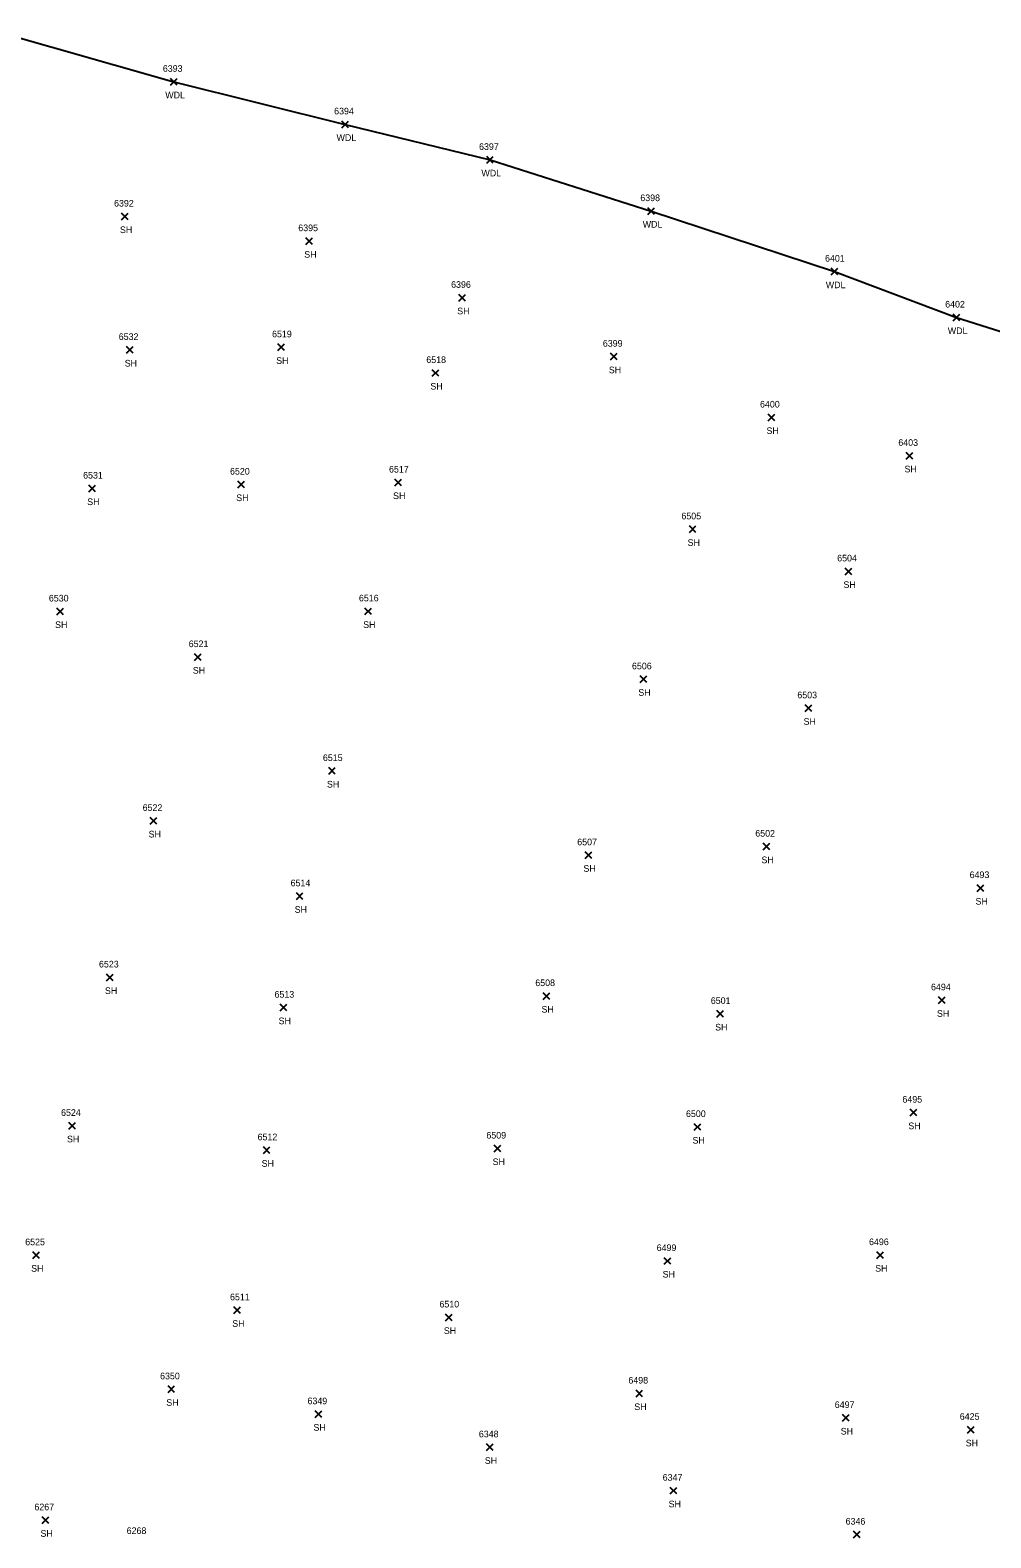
# Model space of a CAD drawing. Extents: x 1678863 to 1683592, y 407783 to 418211.
# Drawn here: x 1679783.6 to 1680073.6, y 409484.1 to 409938.9 of the extents above; entities that cross this region are included whole.
import ezdxf

# ---------------------------------------------------------------- set-up
doc = ezdxf.new("R2010")
doc.units = 0
for name, color, linetype in [('L_A', 7, 'Continuous'), ('L_I', 7, 'Continuous'), ('L_TIC', 7, 'Continuous'), ('LAWA', 7, 'Continuous')]:
    doc.layers.add(name, color=color, linetype=linetype)

msp = doc.modelspace()

# ---------------------------------------------------------------- linework, layer by layer
at = {"layer": 'L_TIC'}
for points in [[(1679825.93, 409922.32), (1679827.93, 409924.32)], [(1679827.93, 409922.32), (1679825.93, 409924.32)], [(1679877.64, 409909.47), (1679879.64, 409911.47)], [(1679879.64, 409909.47), (1679877.64, 409911.47)], [(1679921.38, 409898.77), (1679923.38, 409900.77)], [(1679923.38, 409898.77), (1679921.38, 409900.77)], [(1679811.19, 409881.67), (1679813.19, 409883.67)], [(1679813.19, 409881.67), (1679811.19, 409883.67)], [(1679970.06, 409883.31), (1679972.06, 409885.31)], [(1679972.06, 409883.31), (1679970.06, 409885.31)], [(1679866.82, 409874.25), (1679868.82, 409876.25)], [(1679868.82, 409874.25), (1679866.82, 409876.25)], [(1680025.33, 409865.05), (1680027.33, 409867.05)], [(1680027.33, 409865.05), (1680025.33, 409867.05)], [(1679913, 409857.16), (1679915, 409859.16)], [(1679915, 409857.16), (1679913, 409859.16)], [(1680062.16, 409851.21), (1680064.16, 409853.21)], [(1680064.16, 409851.21), (1680062.16, 409853.21)], [(1679812.62, 409841.42), (1679814.62, 409843.42)], [(1679814.62, 409841.42), (1679812.62, 409843.42)], [(1679858.34, 409842.22), (1679860.34, 409844.22)], [(1679860.34, 409842.22), (1679858.34, 409844.22)], [(1679958.75, 409839.4), (1679960.75, 409841.4)], [(1679960.75, 409839.4), (1679958.75, 409841.4)], [(1679904.89, 409834.47), (1679906.89, 409836.47)], [(1679906.89, 409834.47), (1679904.89, 409836.47)], [(1680006.35, 409821.05), (1680008.35, 409823.05)], [(1680008.35, 409821.05), (1680006.35, 409823.05)], [(1680048.02, 409809.49), (1680050.02, 409811.49)], [(1680050.02, 409809.49), (1680048.02, 409811.49)], [(1679801.3, 409799.62), (1679803.3, 409801.62)], [(1679803.3, 409799.62), (1679801.3, 409801.62)], [(1679846.29, 409800.82), (1679848.29, 409802.82)], [(1679848.29, 409800.82), (1679846.29, 409802.82)], [(1679893.63, 409801.43), (1679895.63, 409803.43)], [(1679895.63, 409801.43), (1679893.63, 409803.43)], [(1679982.55, 409787.32), (1679984.55, 409789.32)], [(1679984.55, 409787.32), (1679982.55, 409789.32)], [(1680029.57, 409774.62), (1680031.57, 409776.62)], [(1680031.57, 409774.62), (1680029.57, 409776.62)], [(1679791.61, 409762.54), (1679793.61, 409764.54)], [(1679793.61, 409762.54), (1679791.61, 409764.54)], [(1679884.6, 409762.57), (1679886.6, 409764.57)], [(1679886.6, 409762.57), (1679884.6, 409764.57)], [(1679833.17, 409748.77), (1679835.17, 409750.77)], [(1679835.17, 409748.77), (1679833.17, 409750.77)], [(1679967.67, 409742.09), (1679969.67, 409744.09)], [(1679969.67, 409742.09), (1679967.67, 409744.09)], [(1680017.53, 409733.34), (1680019.53, 409735.34)], [(1680019.53, 409733.34), (1680017.53, 409735.34)], [(1679873.68, 409714.42), (1679875.68, 409716.42)], [(1679875.68, 409714.42), (1679873.68, 409716.42)], [(1679819.84, 409699.36), (1679821.84, 409701.36)], [(1679821.84, 409699.36), (1679819.84, 409701.36)], [(1680004.83, 409691.6), (1680006.83, 409693.6)], [(1680006.83, 409691.6), (1680004.83, 409693.6)], [(1679951.09, 409689), (1679953.09, 409691)], [(1679953.09, 409689), (1679951.09, 409691)], [(1679863.93, 409676.64), (1679865.93, 409678.64)], [(1679865.93, 409676.64), (1679863.93, 409678.64)], [(1680069.47, 409679.1), (1680071.47, 409681.1)], [(1680071.47, 409679.1), (1680069.47, 409681.1)], [(1679806.65, 409652.14), (1679808.65, 409654.14)], [(1679808.65, 409652.14), (1679806.65, 409654.14)], [(1679938.44, 409646.52), (1679940.44, 409648.52)], [(1679940.44, 409646.52), (1679938.44, 409648.52)], [(1680057.8, 409645.25), (1680059.8, 409647.25)], [(1680059.8, 409645.25), (1680057.8, 409647.25)], [(1679859.07, 409643.03), (1679861.07, 409645.03)], [(1679861.07, 409643.03), (1679859.07, 409645.03)], [(1679990.85, 409641.13), (1679992.85, 409643.13)], [(1679992.85, 409641.13), (1679990.85, 409643.13)], [(1680049.17, 409611.36), (1680051.17, 409613.36)], [(1680051.17, 409611.36), (1680049.17, 409613.36)], [(1679795.21, 409607.38), (1679797.21, 409609.38)], [(1679797.21, 409607.38), (1679795.21, 409609.38)], [(1679984.01, 409607.02), (1679986.01, 409609.02)], [(1679986.01, 409607.02), (1679984.01, 409609.02)], [(1679853.96, 409600.02), (1679855.96, 409602.02)], [(1679855.96, 409600.02), (1679853.96, 409602.02)], [(1679923.68, 409600.53), (1679925.68, 409602.53)], [(1679925.68, 409600.53), (1679923.68, 409602.53)], [(1679784.38, 409568.35), (1679786.38, 409570.35)], [(1679786.38, 409568.35), (1679784.38, 409570.35)], [(1680039.15, 409568.38), (1680041.15, 409570.38)], [(1680041.15, 409568.38), (1680039.15, 409570.38)], [(1679975, 409566.6), (1679977, 409568.6)], [(1679977, 409566.6), (1679975, 409568.6)], [(1679845.07, 409551.74), (1679847.07, 409553.74)], [(1679847.07, 409551.74), (1679845.07, 409553.74)], [(1679908.95, 409549.58), (1679910.95, 409551.58)], [(1679910.95, 409549.58), (1679908.95, 409551.58)], [(1679825.18, 409527.91), (1679827.18, 409529.91)], [(1679827.18, 409527.91), (1679825.18, 409529.91)], [(1679966.45, 409526.63), (1679968.45, 409528.63)], [(1679968.45, 409526.63), (1679966.45, 409528.63)], [(1679869.6, 409520.39), (1679871.6, 409522.39)], [(1679871.6, 409520.39), (1679869.6, 409522.39)], [(1680028.75, 409519.25), (1680030.75, 409521.25)], [(1680030.75, 409519.25), (1680028.75, 409521.25)], [(1680066.49, 409515.69), (1680068.49, 409517.69)], [(1680068.49, 409515.69), (1680066.49, 409517.69)], [(1679921.32, 409510.41), (1679923.32, 409512.41)], [(1679923.32, 409510.41), (1679921.32, 409512.41)], [(1679976.81, 409497.31), (1679978.81, 409499.31)], [(1679978.81, 409497.31), (1679976.81, 409499.31)], [(1679787.2, 409488.4), (1679789.2, 409490.4)], [(1679789.2, 409488.4), (1679787.2, 409490.4)], [(1680032.08, 409484.08), (1680034.08, 409486.08)], [(1680034.08, 409484.08), (1680032.08, 409486.08)]]:
    msp.add_lwpolyline(points, dxfattribs=at)
at = {"layer": 'LAWA'}
msp.add_lwpolyline([(1679772.13, 409938.89), (1679826.93, 409923.32), (1679878.64, 409910.47), (1679922.38, 409899.77), (1679971.06, 409884.31), (1680026.33, 409866.05), (1680063.16, 409852.21), (1680119.91, 409834.32), (1680167.52, 409815.73), (1680215.19, 409801.86), (1680258.97, 409790.94), (1680289.52, 409781.41), (1680315.18, 409768.89), (1680323.05, 409758.38), (1680327.93, 409761.51), (1680342.05, 409772.19), (1680349.85, 409770.79), (1680397.53, 409750.97)], dxfattribs=at)

# ---------------------------------------------------------------- texts
at = {"layer": 'L_A'}
for s, p in [('WDL', (1679824.35, 409918.32)), ('WDL', (1679876.06, 409905.47)), ('WDL', (1679919.79, 409894.77)), ('SH', (1679810.68, 409877.67)), ('WDL', (1679968.48, 409879.31)), ('SH', (1679866.31, 409870.25)), ('WDL', (1680023.74, 409861.05)), ('SH', (1679912.49, 409853.16)), ('WDL', (1680060.57, 409847.21)), ('SH', (1679812.11, 409837.42)), ('SH', (1679857.83, 409838.22)), ('SH', (1679958.24, 409835.4)), ('SH', (1679904.38, 409830.47)), ('SH', (1680005.84, 409817.05)), ('SH', (1680047.5, 409805.49)), ('SH', (1679800.79, 409795.62)), ('SH', (1679845.78, 409796.82)), ('SH', (1679893.12, 409797.43)), ('SH', (1679982.03, 409783.32)), ('SH', (1680029.06, 409770.62)), ('SH', (1679791.1, 409758.54)), ('SH', (1679884.09, 409758.57)), ('SH', (1679832.66, 409744.77)), ('SH', (1679967.16, 409738.09)), ('SH', (1680017.02, 409729.34)), ('SH', (1679873.16, 409710.42)), ('SH', (1679819.32, 409695.36)), ('SH', (1679950.58, 409685)), ('SH', (1680004.32, 409687.6)), ('SH', (1679863.42, 409672.64)), ('SH', (1680068.95, 409675.1)), ('SH', (1679806.14, 409648.14)), ('SH', (1679937.93, 409642.52)), ('SH', (1680057.29, 409641.25)), ('SH', (1679858.56, 409639.03)), ('SH', (1679990.34, 409637.13)), ('SH', (1679794.69, 409603.38)), ('SH', (1680048.66, 409607.36)), ('SH', (1679983.5, 409603.02)), ('SH', (1679853.45, 409596.02)), ('SH', (1679923.17, 409596.53)), ('SH', (1679783.87, 409564.35)), ('SH', (1679974.49, 409562.6)), ('SH', (1680038.64, 409564.38)), ('SH', (1679844.56, 409547.74)), ('SH', (1679908.44, 409545.58)), ('SH', (1679824.67, 409523.91)), ('SH', (1679965.94, 409522.63)), ('SH', (1679869.09, 409516.39)), ('SH', (1680028.24, 409515.25)), ('SH', (1680065.98, 409511.69)), ('SH', (1679920.81, 409506.41)), ('SH', (1679976.3, 409493.31)), ('SH', (1679786.69, 409484.4))]:
    msp.add_text(s, height=2, dxfattribs=at).set_placement(p)
at = {"layer": 'L_I'}
for s, p in [('6393', (1679823.62, 409926.32)), ('6394', (1679875.33, 409913.47)), ('6397', (1679919.07, 409902.77)), ('6392', (1679808.89, 409885.67)), ('6398', (1679967.75, 409887.31)), ('6395', (1679864.51, 409878.25)), ('6401', (1680023.51, 409869.05)), ('6396', (1679910.64, 409861.16)), ('6402', (1680059.77, 409855.21)), ('6532', (1679810.31, 409845.42)), ('6519', (1679856.59, 409846.22)), ('6399', (1679956.44, 409843.4)), ('6518', (1679903.15, 409838.47)), ('6400', (1680003.88, 409825.05)), ('6403', (1680045.63, 409813.49)), ('6531', (1679799.56, 409803.62)), ('6520', (1679843.9, 409804.82)), ('6517', (1679891.89, 409805.43)), ('6505', (1679980.16, 409791.32)), ('6504', (1680027.18, 409778.62)), ('6530', (1679789.22, 409766.54)), ('6516', (1679882.81, 409766.57)), ('6521', (1679831.43, 409752.77)), ('6506', (1679965.23, 409746.09)), ('6503', (1680015.15, 409737.34)), ('6515', (1679871.94, 409718.42)), ('6522', (1679817.53, 409703.36)), ('6502', (1680002.45, 409695.6)), ('6507', (1679948.71, 409693)), ('6514', (1679862.19, 409680.64)), ('6493', (1680067.16, 409683.1)), ('6523', (1679804.34, 409656.14)), ('6508', (1679936.05, 409650.52)), ('6494', (1680055.5, 409649.25)), ('6513', (1679857.33, 409647.03)), ('6501', (1679989.03, 409645.13)), ('6495', (1680046.87, 409615.36)), ('6524', (1679792.9, 409611.38)), ('6500', (1679981.54, 409611.02)), ('6512', (1679852.22, 409604.02)), ('6509', (1679921.29, 409604.53)), ('6525', (1679782.08, 409572.35)), ('6496', (1680036.79, 409572.38)), ('6499', (1679972.69, 409570.6)), ('6511', (1679843.9, 409555.74)), ('6510', (1679907.12, 409553.58)), ('6350', (1679822.79, 409531.91)), ('6498', (1679964.15, 409530.63)), ('6349', (1679867.29, 409524.39)), ('6497', (1680026.45, 409523.25)), ('6425', (1680064.18, 409519.69)), ('6348', (1679919.01, 409514.41)), ('6347', (1679974.5, 409501.31)), ('6267', (1679784.85, 409492.4)), ('6268', (1679812.7, 409485.24)), ('6346', (1680029.72, 409488.08))]:
    msp.add_text(s, height=2, dxfattribs=at).set_placement(p)

doc.saveas('drawing.dxf')
